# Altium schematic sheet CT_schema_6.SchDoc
size 368 x 336 mm
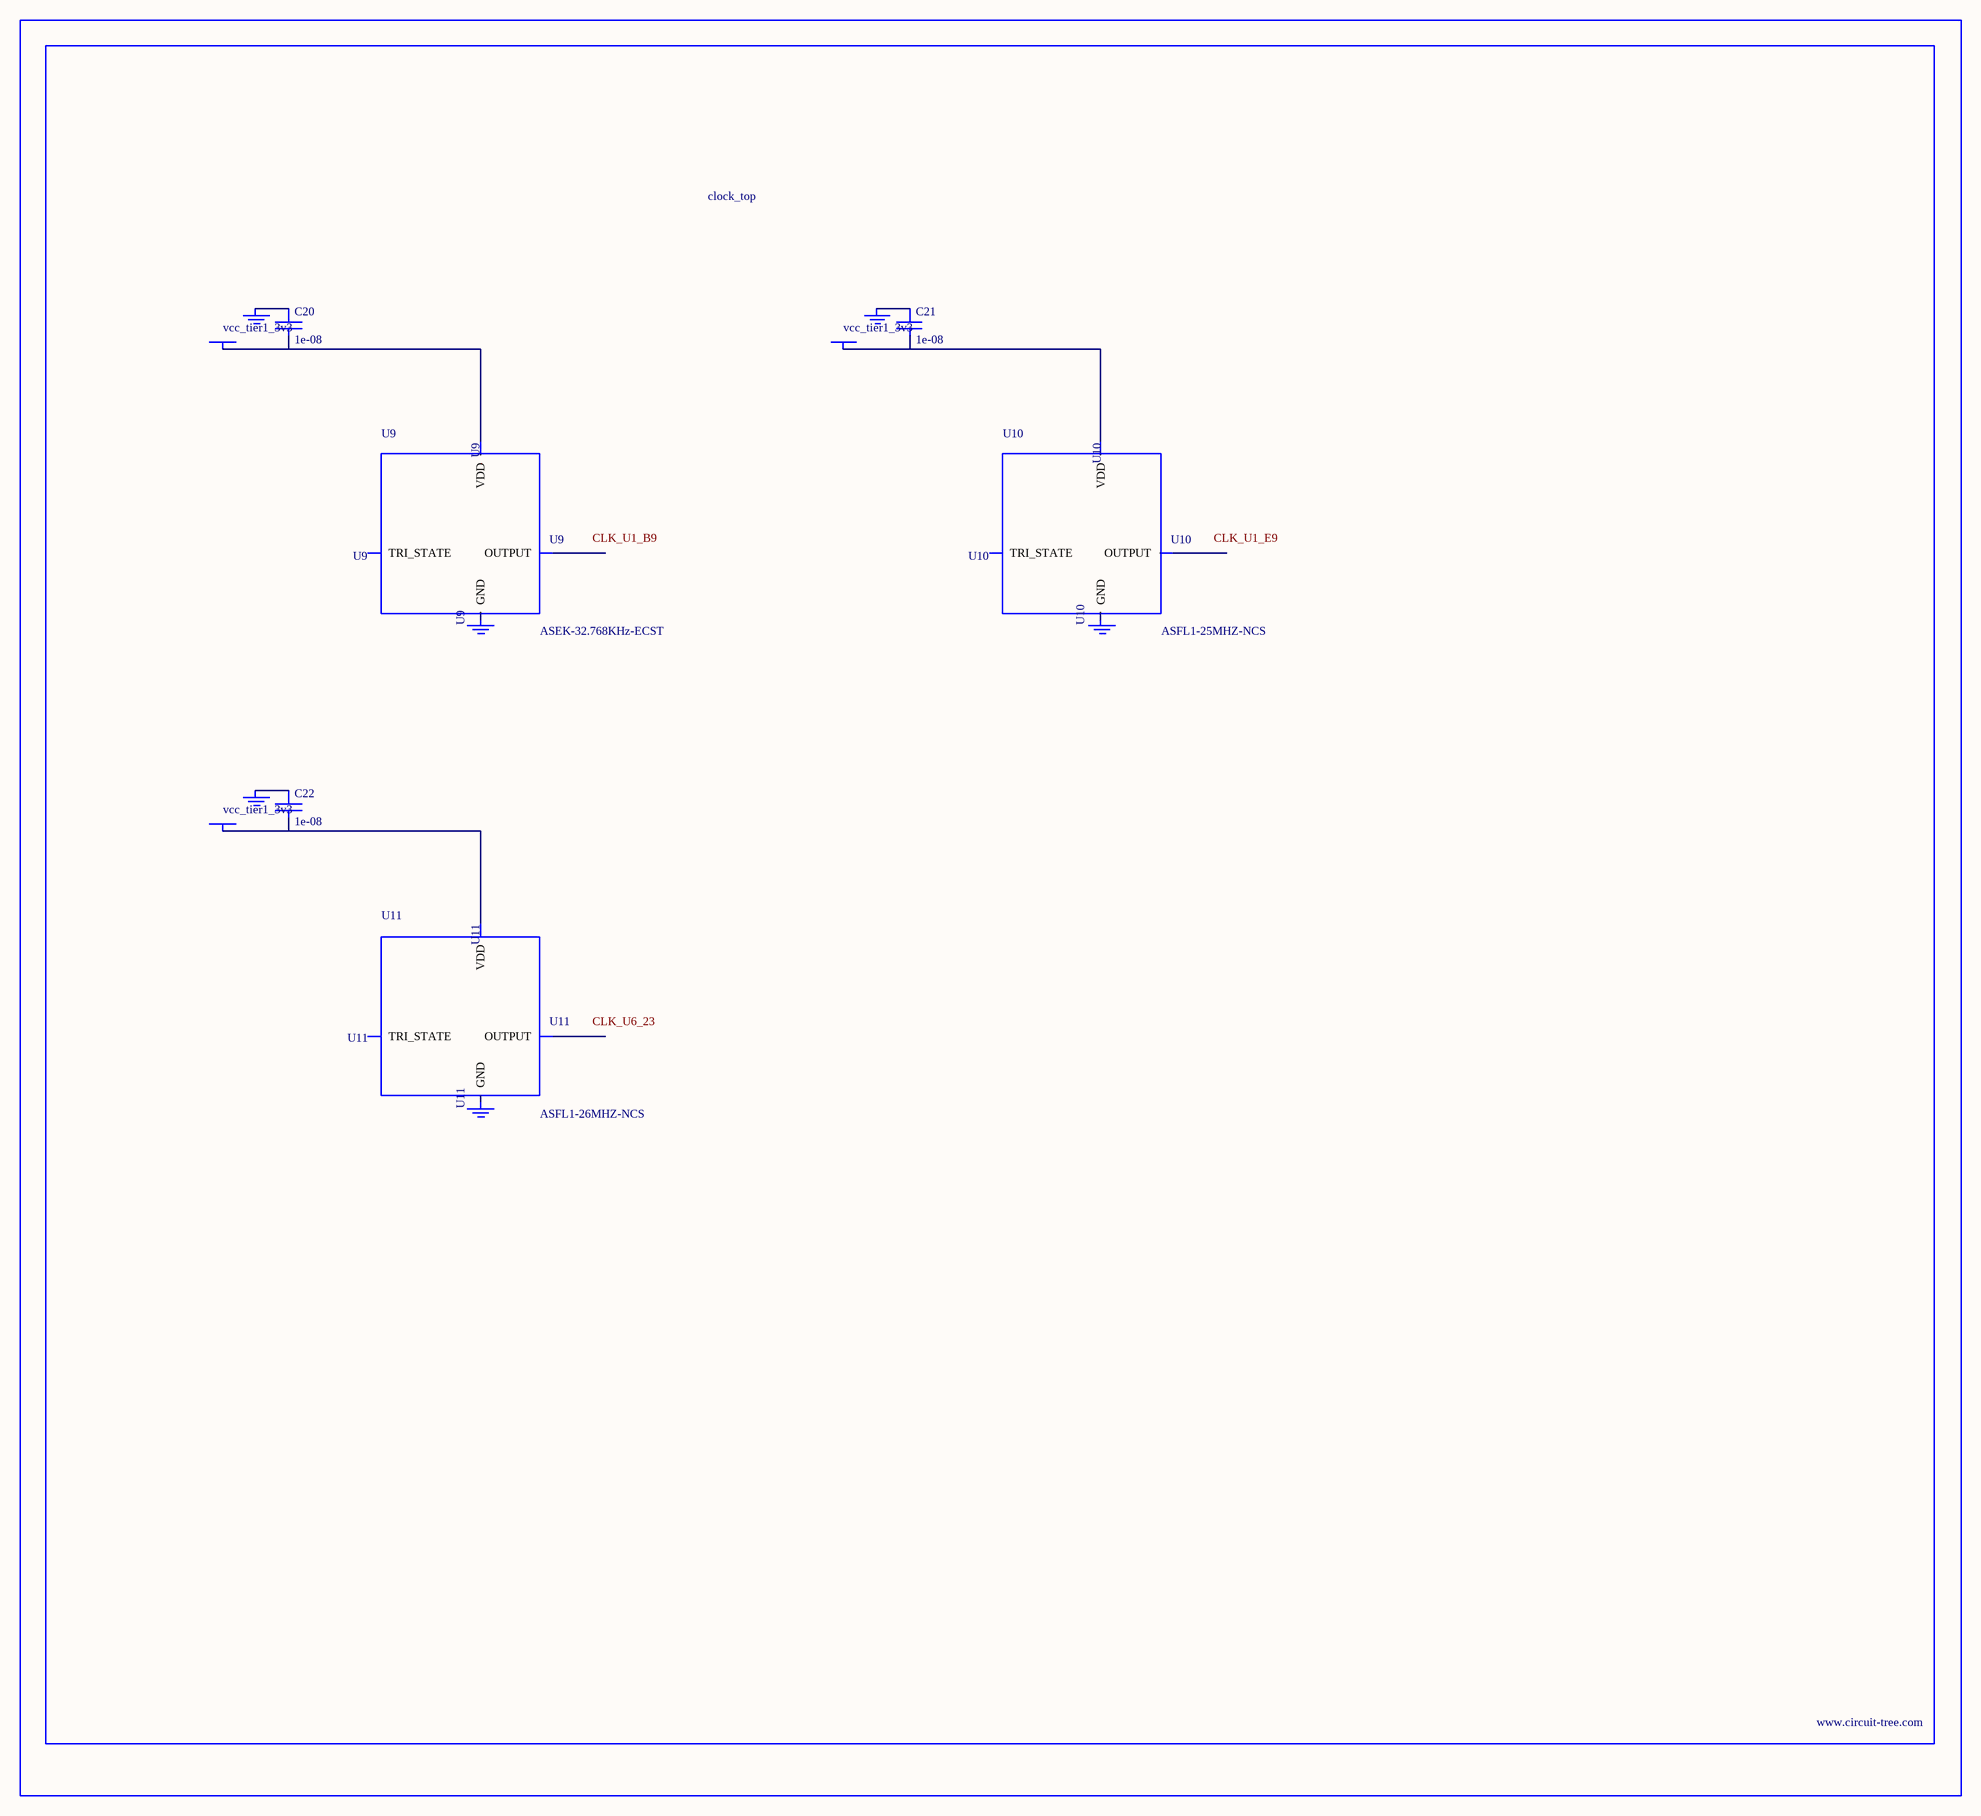
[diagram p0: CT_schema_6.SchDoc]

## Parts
BORDER5  (no value)
C20  1e-08  [C0402]
C21  1e-08  [C0402]
C22  1e-08  [C0402]
GND_INSTANCE_5_0  (no value)
GND_INSTANCE_5_1  (no value)
GND_INSTANCE_5_2  (no value)
GND_INSTANCE_5_3  (no value)
GND_INSTANCE_5_4  (no value)
GND_INSTANCE_5_5  (no value)
POWER_INSTANCE_5_0  vcc_tier1_3v3
POWER_INSTANCE_5_1  vcc_tier1_3v3
POWER_INSTANCE_5_2  vcc_tier1_3v3
U9  ASEK-32.768KHz-ECST  [ASEK]
U10  ASFL1-25MHZ-NCS  [ASFL1]
U11  ASFL1-26MHZ-NCS  [ASFL1]

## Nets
NetC20_1: C20.1 GND_INSTANCE_5_0.0(GND)
NetC20_2: C20.2 POWER_INSTANCE_5_0.0(PWR) U9.4(VDD)
NetC21_1: C21.1 GND_INSTANCE_5_2.0(GND)
NetC21_2: C21.2 POWER_INSTANCE_5_1.0(PWR) U10.4(VDD)
NetC22_1: C22.1 GND_INSTANCE_5_4.0(GND)
NetC22_2: C22.2 POWER_INSTANCE_5_2.0(PWR) U11.4(VDD)

Not connected (* = marked no-connect by the designer): GND_INSTANCE_5_1 0(GND); GND_INSTANCE_5_3 0(GND); GND_INSTANCE_5_5 0(GND); U9 1(TRI_STATE) 2(GND) 3(OUTPUT); U10 1(TRI_STATE) 2(GND) 3(OUTPUT); U11 1(TRI_STATE) 2(GND) 3(OUTPUT)

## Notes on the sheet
- Labels drawn without touching a wire or pin: CLK_U1_B9, CLK_U1_E9, CLK_U6_23

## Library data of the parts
BORDER5 = BORDER_PAGE5
C20-C22 = C0402C103K3RAC
GND_INSTANCE_5_0-GND_INSTANCE_5_5 = GND
POWER_INSTANCE_5_0-POWER_INSTANCE_5_2 = PWR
